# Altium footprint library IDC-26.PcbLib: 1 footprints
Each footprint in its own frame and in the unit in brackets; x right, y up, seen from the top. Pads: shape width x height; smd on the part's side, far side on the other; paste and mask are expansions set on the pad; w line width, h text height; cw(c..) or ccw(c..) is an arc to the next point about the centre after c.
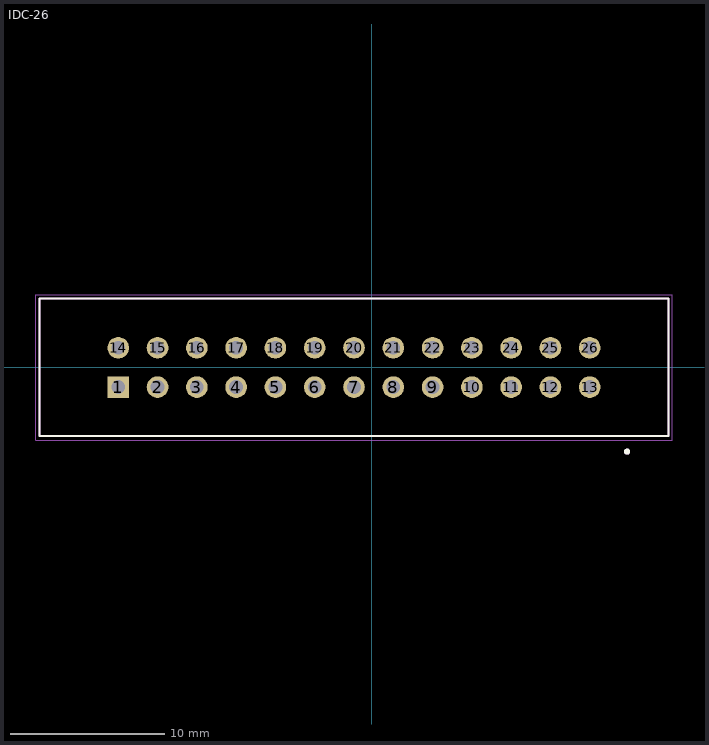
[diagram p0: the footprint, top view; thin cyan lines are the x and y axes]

## IDC-26 [mil]
pads (26):
  rect 55.04x55.04 hole 35.04: 1(-645,-50)
  round 55.04 hole 35.04: 2(-545,-50) 3(-445,-50) 4(-345,-50) 5(-245,-50) 6(-145,-50) 7(-45,-50) 8(55,-50) 9(155,-50) 10(255,-50) 11(355,-50) 12(455,-50) 13(555,-50) 14(-645,50) 15(-545,50) 16(-445,50) 17(-345,50) 18(-245,50) 19(-145,50) 20(-45,50) 21(55,50) 22(155,50) 23(255,50) 24(355,50) 25(455,50) 26(555,50)
Top Overlay:
  circle w7.87: c650,-214.37 r3.94
  lines w5: -845,-175 -845,175 755,175 755,-175 -845,-175
Mechanical 13:
  circle w7.87: c650,-214.37 r3.94
  lines w5: -845,-175 -845,175 755,175 755,-175 -845,-175
Mechanical 15:
  lines w1.97: -854.84,-184.84 764.84,-184.84 764.84,184.84 -854.84,184.84 -854.84,-184.84
3D body "IDC-26.STEP": height 353, standoff -175, extent -845,-185 755,177.82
